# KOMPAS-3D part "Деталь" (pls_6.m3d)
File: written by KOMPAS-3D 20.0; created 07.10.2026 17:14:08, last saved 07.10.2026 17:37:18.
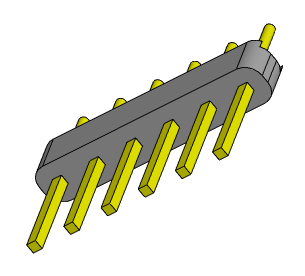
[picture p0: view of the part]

Document properties: Полное имя файла: D:\myProjects\Progect_esp32\box_compas\разъемы\pls_6.m3d

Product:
- Part/product: Деталь
    Масса: 0.000766031
  - Body: Тело 1
      Масса: 0.00078211

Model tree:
1. Эскиз:1
2. Элемент выдавливания:1
     Расстояние 1 = 2.5
3. Эскиз:2  (with: Элемент выдавливания:1)
4. Элемент выдавливания:2
     Расстояние 1 = 6
5. Массив по сетке:1  (with: Элемент выдавливания:2, Эскиз:2)  (6 pattern instances)
     Шаг 1 = 2.54; Угол раствора = 90
6. Эскиз:3  (with: Элемент выдавливания:1)
7. Элемент выдавливания:3
     Расстояние 1 = 3
8. Массив по сетке:2  (with: Элемент выдавливания:3, Эскиз:3)  (6 pattern instances)
     Шаг 1 = 2.54; Угол раствора = 90; Геометрический массив = 128
9. Эскиз:4  (with: Элемент выдавливания:1)
10. Элемент выдавливания:4
     Расстояние 2 = 15.24
11. Скругление:1  (with: Элемент выдавливания:1)
     Радиус = 1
